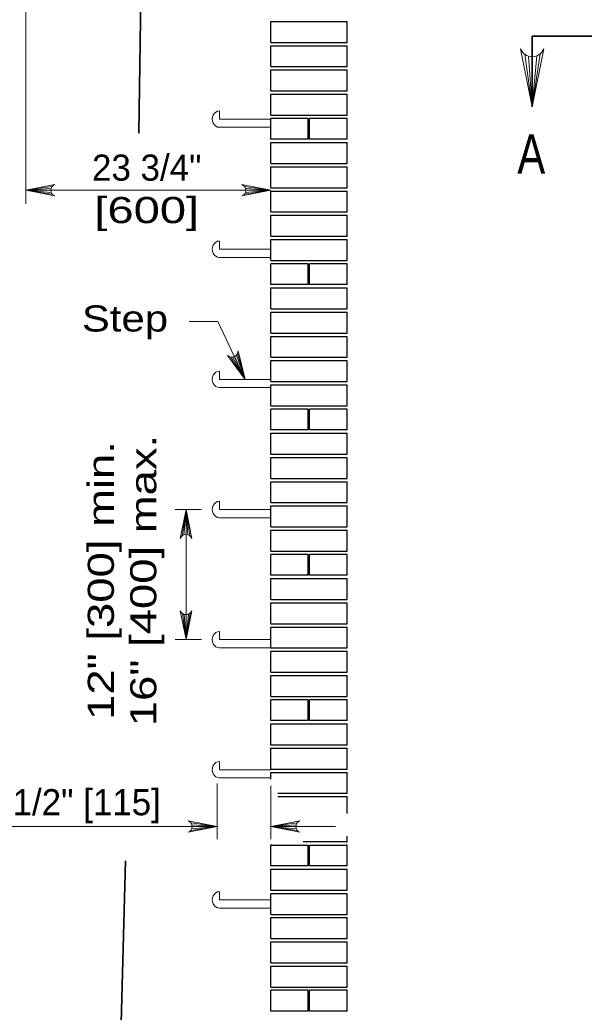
# Model space of a CAD drawing. Extents: x 750.7 to 784.7, y 860.1 to 882.1.
# Drawn here: x 763.34 to 766.8, y 872.53 to 878.6 of the extents above; entities that cross this region are included whole.
import ezdxf
from ezdxf.enums import TextEntityAlignment as Align

# ---------------------------------------------------------------- set-up
doc = ezdxf.new("R2010")
doc.units = 0
doc.header["$LTSCALE"] = 0.064
doc.layers.add('1', color=7, linetype='Continuous', lineweight=13)

msp = doc.modelspace()

# ---------------------------------------------------------------- linework, layer by layer
at = {"layer": '1'}
for p, q in [((763.37542, 879.93708), (763.37542, 877.47533)), ((766.43358, 878.38975), (766.47842, 878.06917)), ((766.45575, 878.37892), (766.47842, 878.06917)), ((766.528, 878.3935), (766.47842, 878.06917)), ((766.50725, 878.38125), (766.47842, 878.06917)), ((766.47842, 878.37558), (766.47842, 878.06917)), ((764.56192, 877.99342), (764.56192, 878.0435)), ((764.56192, 877.99342), (764.87642, 877.99342)), ((764.56192, 877.94333), (764.87642, 877.94333)), ((763.53575, 877.58058), (763.37542, 877.55817)), ((763.53033, 877.5695), (763.37542, 877.55817)), ((764.71617, 877.58058), (764.8765, 877.55817)), ((764.72158, 877.5695), (764.8765, 877.55817)), ((763.52867, 877.55817), (763.37542, 877.55817)), ((763.5315, 877.54375), (763.37542, 877.55817)), ((763.53767, 877.53342), (763.37542, 877.55817)), ((763.37542, 877.55817), (764.8765, 877.55817)), ((764.71425, 877.53342), (764.8765, 877.55817)), ((764.72042, 877.54375), (764.8765, 877.55817)), ((764.72325, 877.55817), (764.8765, 877.55817)), ((764.56192, 877.19683), (764.56192, 877.24692)), ((764.56192, 877.19683), (764.87642, 877.19683)), ((764.56192, 877.14675), (764.87642, 877.14675)), ((764.376, 876.75383), (764.55125, 876.75383)), ((764.71917, 876.40025), (764.55125, 876.75383)), ((764.63108, 876.53608), (764.71917, 876.40025)), ((764.64342, 876.53583), (764.71917, 876.40025)), ((764.71917, 876.40025), (764.65133, 876.54575)), ((764.65442, 876.53917), (764.71917, 876.40025)), ((764.66625, 876.54783), (764.71917, 876.40025)), ((764.67317, 876.55775), (764.71917, 876.40025)), ((764.56192, 876.40025), (764.56192, 876.45033)), ((764.56192, 876.40025), (764.87642, 876.40025)), ((764.56192, 876.35017), (764.87642, 876.35017)), ((764.56192, 875.60367), (764.56192, 875.65375)), ((764.45225, 875.6035), (764.2915, 875.6035)), ((764.33283, 875.44125), (764.35758, 875.6035)), ((764.34317, 875.44742), (764.35758, 875.6035)), ((764.35758, 875.6035), (764.35758, 874.80692)), ((764.35758, 875.45025), (764.35758, 875.6035)), ((764.36892, 875.44858), (764.35758, 875.6035)), ((764.38, 875.44317), (764.35758, 875.6035)), ((764.56192, 875.60367), (764.87642, 875.60367)), ((764.56192, 875.55358), (764.87642, 875.55358)), ((764.33517, 874.96725), (764.35758, 874.80692)), ((764.34625, 874.96175), (764.35758, 874.80692)), ((764.38242, 874.96908), (764.35758, 874.80692)), ((764.372, 874.963), (764.35758, 874.80692)), ((764.35758, 874.96017), (764.35758, 874.80692)), ((764.56192, 874.80708), (764.56192, 874.85717)), ((764.45225, 874.80692), (764.2915, 874.80692)), ((764.56192, 874.80708), (764.87642, 874.80708)), ((764.56192, 874.757), (764.87642, 874.757)), ((764.56192, 874.0105), (764.56192, 874.06058)), ((764.56192, 874.0105), (764.87642, 874.0105)), ((764.54833, 873.58458), (764.54833, 873.92717)), ((764.56192, 873.96042), (764.87642, 873.96042)), ((764.8765, 873.91225), (764.8765, 873.58458)), ((764.388, 873.68533), (764.54833, 873.66292)), ((765.03742, 873.68533), (764.87708, 873.66292)), ((764.54833, 873.66292), (763.10292, 873.66292)), ((764.38617, 873.63817), (764.54833, 873.66292)), ((764.39225, 873.6485), (764.54833, 873.66292)), ((764.3935, 873.67425), (764.54833, 873.66292)), ((764.39508, 873.66292), (764.54833, 873.66292)), ((765.032, 873.67425), (764.87708, 873.66292)), ((765.03033, 873.66292), (764.87708, 873.66292)), ((765.03317, 873.6485), (764.87708, 873.66292)), ((765.03925, 873.63817), (764.87708, 873.66292)), ((764.9205, 873.66283), (765.27308, 873.66283)), ((764.56192, 873.21392), (764.56192, 873.264)), ((764.56192, 873.21392), (764.87642, 873.21392)), ((764.56192, 873.16383), (764.87642, 873.16383))]:
    msp.add_line(p, q, dxfattribs=at)
at = {"layer": '1', "lineweight": 35}
for p, q in [((764.06808, 877.90742), (764.09633, 879.80392)), ((766.97333, 878.502), (766.47842, 878.502)), ((766.47842, 878.502), (766.47842, 878.06917)), ((763.83808, 868.0415), (763.98708, 873.45325))]:
    msp.add_line(p, q, dxfattribs=at)
at = {"layer": '1', "lineweight": 25}
for p, q in [((764.8765, 877.86975), (764.8765, 877.99783)), ((765.114, 877.86975), (765.114, 877.99783)), ((765.10658, 877.86975), (764.8765, 877.86975)), ((765.34417, 877.86975), (765.114, 877.86975)), ((764.8765, 876.98017), (764.8765, 877.10825)), ((765.114, 876.98017), (765.114, 877.10825)), ((765.10658, 876.98017), (764.8765, 876.98017)), ((765.34417, 876.98017), (765.114, 876.98017)), ((764.8765, 876.09058), (764.8765, 876.21867)), ((765.11408, 876.09058), (765.114, 876.21867)), ((765.10658, 876.09058), (764.8765, 876.09058)), ((765.34417, 876.09058), (765.11408, 876.09058)), ((764.8765, 875.201), (764.8765, 875.32908)), ((765.114, 875.201), (765.114, 875.32908)), ((765.10658, 875.201), (764.8765, 875.201)), ((765.34417, 875.201), (765.114, 875.201)), ((764.8765, 874.54225), (764.8765, 874.58775)), ((764.8765, 874.31142), (764.8765, 874.43942)), ((765.114, 874.31142), (765.114, 874.43942)), ((765.10658, 874.31142), (765.10658, 874.35967)), ((765.11408, 874.31142), (765.11408, 874.3565)), ((765.34417, 874.31142), (765.34417, 874.39317)), ((764.8765, 874.31142), (764.8765, 874.33233)), ((765.10658, 874.31142), (764.8765, 874.31142)), ((765.10658, 874.31142), (764.8765, 874.31142)), ((765.34417, 874.31142), (765.114, 874.31142)), ((765.34417, 874.31142), (765.11408, 874.31142)), ((764.9205, 873.84642), (765.34417, 873.84642)), ((765.34417, 873.74367), (765.34417, 873.84642)), ((765.33942, 873.57008), (765.07467, 873.57008)), ((765.33942, 873.57008), (765.34417, 873.57008)), ((765.34417, 873.57008), (765.34417, 873.60367)), ((764.88383, 873.54983), (764.8765, 873.54983)), ((765.10658, 873.42183), (765.10658, 873.54983)), ((765.114, 873.42183), (765.114, 873.54983)), ((765.114, 873.54983), (765.33942, 873.54983)), ((765.10658, 873.42183), (764.8765, 873.42183)), ((765.34417, 873.42183), (765.114, 873.42183)), ((764.8765, 872.53217), (764.8765, 872.66025)), ((765.114, 872.53217), (765.114, 872.66025)), ((765.10658, 872.53217), (764.8765, 872.53217)), ((765.34417, 872.53217), (765.114, 872.53217))]:
    msp.add_line(p, q, dxfattribs=at)
for points in [[(764.8765, 878.46283), (764.8765, 878.59092), (765.34417, 878.59092)], [(764.8765, 878.46283), (765.34417, 878.46283), (765.34417, 878.59092)], [(764.8765, 878.31458), (764.8765, 878.44267), (765.34417, 878.44267)], [(764.8765, 878.31458), (765.34417, 878.31458), (765.34417, 878.44267)], [(764.8765, 878.16633), (764.8765, 878.29433), (765.34417, 878.29433)], [(764.8765, 878.16633), (765.34417, 878.16633), (765.34417, 878.29433)], [(764.8765, 878.01808), (764.8765, 878.14608), (765.34417, 878.14608)], [(764.8765, 878.01808), (765.34417, 878.01808), (765.34417, 878.14608)], [(765.10658, 877.86975), (765.10658, 877.99783), (764.8765, 877.99783)], [(765.34417, 877.86975), (765.34417, 877.99783), (765.114, 877.99783)], [(764.8765, 877.7215), (764.8765, 877.84958), (765.34417, 877.84958)], [(764.8765, 877.7215), (765.34417, 877.7215), (765.34417, 877.84958)], [(764.8765, 877.57325), (764.8765, 877.70133), (765.34417, 877.70133)], [(764.8765, 877.57325), (765.34417, 877.57325), (765.34417, 877.70133)], [(764.8765, 877.425), (764.8765, 877.553), (765.34417, 877.553)], [(764.8765, 877.425), (765.34417, 877.425), (765.34417, 877.553)], [(764.8765, 877.27675), (764.8765, 877.40475), (765.34417, 877.40475)], [(764.8765, 877.27675), (765.34417, 877.27675), (765.34417, 877.40475)], [(764.8765, 877.12842), (764.8765, 877.2565), (765.34417, 877.2565)], [(764.8765, 877.12842), (765.34417, 877.12842), (765.34417, 877.2565)], [(765.10658, 876.98017), (765.10658, 877.10825), (764.8765, 877.10825)], [(765.34417, 876.98017), (765.34417, 877.10825), (765.114, 877.10825)], [(764.8765, 876.83192), (764.8765, 876.96), (765.34417, 876.96)], [(764.8765, 876.83192), (765.34417, 876.83192), (765.34417, 876.96)], [(764.8765, 876.68367), (764.8765, 876.81175), (765.34417, 876.81175)], [(764.8765, 876.68367), (765.34417, 876.68367), (765.34417, 876.81175)], [(764.8765, 876.53542), (764.8765, 876.66342), (765.34417, 876.66342)], [(764.8765, 876.53542), (765.34417, 876.53542), (765.34417, 876.66342)], [(764.8765, 876.38708), (764.8765, 876.51517), (765.34417, 876.51517)], [(764.8765, 876.38708), (765.34417, 876.38708), (765.34417, 876.51517)], [(764.8765, 876.23883), (764.8765, 876.36692), (765.34417, 876.36692)], [(764.8765, 876.23883), (765.34417, 876.23883), (765.34417, 876.36692)], [(765.10658, 876.09058), (765.10658, 876.21867), (764.8765, 876.21867)], [(765.34417, 876.09058), (765.34417, 876.21867), (765.114, 876.21867)], [(764.8765, 875.94233), (764.8765, 876.07042), (765.34417, 876.07042)], [(764.8765, 875.94233), (765.34417, 875.94233), (765.34417, 876.07042)], [(764.8765, 875.79408), (764.8765, 875.92208), (765.34417, 875.92208)], [(764.8765, 875.79408), (765.34417, 875.79408), (765.34417, 875.92208)], [(764.8765, 875.64583), (764.8765, 875.77383), (765.34417, 875.77383)], [(764.8765, 875.64583), (765.34417, 875.64583), (765.34417, 875.77383)], [(764.8765, 875.4975), (764.8765, 875.62558), (765.34417, 875.62558)], [(764.8765, 875.4975), (765.34417, 875.4975), (765.34417, 875.62558)], [(764.8765, 875.34925), (764.8765, 875.47733), (765.34417, 875.47733)], [(764.8765, 875.34925), (765.34417, 875.34925), (765.34417, 875.47733)], [(765.10658, 875.201), (765.10658, 875.32908), (764.8765, 875.32908)], [(765.34417, 875.201), (765.34417, 875.32908), (765.114, 875.32908)], [(764.8765, 875.05275), (764.8765, 875.18075), (765.34417, 875.18075)], [(764.8765, 875.05275), (765.34417, 875.05275), (765.34417, 875.18075)], [(764.8765, 874.9045), (764.8765, 875.0325), (765.34417, 875.0325)], [(764.8765, 874.9045), (765.34417, 874.9045), (765.34417, 875.0325)], [(764.8765, 874.75617), (764.8765, 874.88425), (765.34417, 874.88425)], [(764.8765, 874.75617), (765.34417, 874.75617), (765.34417, 874.88425)], [(764.8765, 874.60792), (764.8765, 874.736), (765.34417, 874.736)], [(764.8765, 874.60792), (765.34417, 874.60792), (765.34417, 874.736)], [(764.8765, 874.45967), (764.8765, 874.58775), (765.34417, 874.58775)], [(764.8765, 874.45967), (765.34417, 874.45967), (765.34417, 874.58775)], [(765.10658, 874.31142), (765.10658, 874.43942), (764.8765, 874.43942)], [(765.34417, 874.31142), (765.34417, 874.43942), (765.114, 874.43942)], [(764.8765, 874.16317), (764.8765, 874.29117), (765.34417, 874.29117)], [(764.8765, 874.16317), (765.34417, 874.16317), (765.34417, 874.29117)], [(764.8765, 874.01483), (764.8765, 874.14292), (765.34417, 874.14292)], [(764.8765, 874.01483), (765.34417, 874.01483), (765.34417, 874.14292)], [(764.8765, 873.95375), (764.8765, 873.99467), (765.34417, 873.99467)], [(764.9205, 873.86658), (765.34417, 873.86658), (765.34417, 873.99467)], [(764.8765, 873.42183), (764.8765, 873.54983), (765.10658, 873.54983)], [(765.34417, 873.42183), (765.34417, 873.54983), (765.33942, 873.54983)], [(764.8765, 873.27358), (764.8765, 873.40158), (765.34417, 873.40158)], [(764.8765, 873.27358), (765.34417, 873.27358), (765.34417, 873.40158)], [(764.8765, 873.12525), (764.8765, 873.25333), (765.34417, 873.25333)], [(764.8765, 873.12525), (765.34417, 873.12525), (765.34417, 873.25333)], [(764.8765, 872.977), (764.8765, 873.10508), (765.34417, 873.10508)], [(764.8765, 872.977), (765.34417, 872.977), (765.34417, 873.10508)], [(764.8765, 872.82875), (764.8765, 872.95683), (765.34417, 872.95683)], [(764.8765, 872.82875), (765.34417, 872.82875), (765.34417, 872.95683)], [(764.8765, 872.6805), (764.8765, 872.8085), (765.34417, 872.8085)], [(764.8765, 872.6805), (765.34417, 872.6805), (765.34417, 872.8085)], [(765.10658, 872.53217), (765.10658, 872.66025), (764.8765, 872.66025)], [(765.34417, 872.53217), (765.34417, 872.66025), (765.114, 872.66025)]]:
    msp.add_lwpolyline(points, dxfattribs=at)
at = {"layer": '1'}
for points in [[(766.54925, 878.42325), (766.47842, 878.06917), (766.40758, 878.42325)], [(763.5525, 877.52275), (763.37542, 877.55817), (763.5525, 877.59358)], [(764.69942, 877.52275), (764.8765, 877.55817), (764.69942, 877.59358)], [(764.67642, 876.57575), (764.71917, 876.40025), (764.61225, 876.54575)], [(764.32217, 875.42642), (764.35758, 875.6035), (764.393, 875.42642)], [(764.393, 874.984), (764.35758, 874.80692), (764.32217, 874.984)], [(764.37125, 873.6275), (764.54833, 873.66292), (764.37125, 873.69833)], [(765.05417, 873.6275), (764.87708, 873.66292), (765.05417, 873.69833)]]:
    msp.add_lwpolyline(points, dxfattribs=at)
for centre, radius, start, end in [((766.47834, 878.45188), 0.07644, 202.08782, 337.91395), ((763.5668, 877.55822), 0.03822, 112.08782, 247.91395), ((764.68511, 877.55822), 0.03822, 292.08605, 67.91218), ((764.63829, 876.5737), 0.03822, 227.08113, 2.90726), ((764.35762, 875.4121), 0.03822, 22.08782, 157.91395), ((764.35755, 874.99827), 0.03822, 202.08782, 337.91395), ((764.35697, 873.66296), 0.03822, 292.08605, 67.91218), ((765.06846, 873.66296), 0.03822, 112.08782, 247.91395)]:
    msp.add_arc(centre, radius, start, end, dxfattribs=at)
for centre in [(764.56192, 877.99342), (764.56192, 877.19684), (764.56192, 876.40025), (764.56192, 875.60367), (764.56192, 874.80708), (764.56192, 874.0105), (764.56192, 873.21392)]:
    msp.add_ellipse(centre, major_axis=(0, 0.05012), ratio=0.869565, start_param=0.000003, end_param=3.1415958, dxfattribs=at)

# ---------------------------------------------------------------- texts
for s, height, width, p in [('A', 0.24, 0.8, (766.38725, 877.65942)), ('Step', 0.16, 1.2, (763.71917, 876.693))]:
    msp.add_text(s, height=height, dxfattribs=dict(at, width=width)).set_placement(p)
msp.add_text('23 3/4"', height=0.16, dxfattribs=at).set_placement((764.11667, 877.6165), align=Align.CENTER)
at = {"layer": '1', "width": 1.35}
msp.add_text('[600]', height=0.16, dxfattribs=at).set_placement((764.11667, 877.3565), align=Align.CENTER)
at = {"layer": '1', "width": 1.3}
for s, p in [('12" [300] min.', (763.91533, 875.16892)), ('16" [400] max.', (764.17533, 875.16892))]:
    msp.add_text(s, height=0.16, rotation=90, dxfattribs=at).set_placement(p, align=Align.CENTER)
at = {"layer": '1'}
msp.add_text('4 1/2" [115]', height=0.16, dxfattribs=at).set_placement((763.116, 873.73175))

doc.saveas('drawing.dxf')
